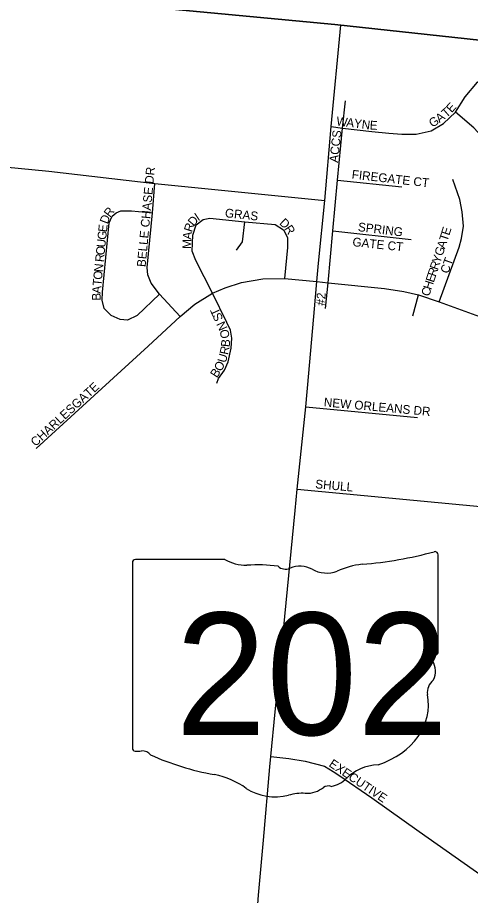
# Model space of a CAD drawing. Extents: x 8.5 to 81.5, y -1.2 to 22.4.
# Drawn here: x 55.233 to 55.722, y 18.242 to 19.189 of the extents above; entities that cross this region are included whole.
import ezdxf

# ---------------------------------------------------------------- set-up
doc = ezdxf.new("R2010")
doc.units = 0
for name, color, linetype in [('GM_X_Adjacent_County', 7, 'Continuous'), ('GM_X_City_Street', 7, 'Continuous'), ('GM_X_City_Street_Text', 7, 'Continuous'), ('GM_X_County', 7, 'Continuous'), ('GM_X_State_Location', 7, 'Continuous'), ('GM_X_State_Route', 7, 'Continuous'), ('GM_X_State_Shield', 7, 'Continuous')]:
    doc.layers.add(name, color=color, linetype=linetype)

msp = doc.modelspace()

# ---------------------------------------------------------------- linework, layer by layer
at = {"layer": 'GM_X_Adjacent_County'}
msp.add_lwpolyline([(54.08792, 21.25055), (53.97517, 21.07964), (53.98925, 20.88787), (54.01131, 20.79217), (54.0509, 20.40525), (54.08743, 20.21352), (54.08516, 20.02178), (54.11826, 19.92611), (54.16353, 19.83082), (54.25825, 19.73401), (54.36439, 19.53926), (54.43857, 19.4436), (54.4557, 19.28681), (54.60716, 19.27259), (55.07099, 19.22961), (55.57538, 19.18184), (55.8177, 19.15565), (56.1419, 19.12062), (56.17199, 19.11737), (56.25272, 19.11082)], dxfattribs=at)
at = {"layer": 'GM_X_City_Street'}
for points in [[(55.57169, 19.07164), (55.58369, 19.07004), (55.61533, 19.06632), (55.63356, 19.06446), (55.64763, 19.06333), (55.66318, 19.06333), (55.67948, 19.06707), (55.69249, 19.07514), (55.70565, 19.08725), (55.71609, 19.10365), (55.72942, 19.11965), (55.7381, 19.12632), (55.75171, 19.13271), (55.76667, 19.13571), (55.7891, 19.13416), (55.81595, 19.1323), (55.8506, 19.12851), (55.8694, 19.12674), (55.88226, 19.12419), (55.89348, 19.11971), (55.90379, 19.11373), (55.91729, 19.10309)], [(55.56538, 18.8755), (55.56829, 18.90321), (55.57316, 18.9591), (55.57842, 19.0138), (55.58369, 19.07004), (55.58695, 19.09958)], [(55.73939, 18.86377), (55.76029, 18.91778), (55.76526, 18.9366), (55.7684, 18.95462), (55.76918, 18.97077), (55.76715, 18.99145), (55.76511, 19.00148), (55.76291, 19.01104), (55.75461, 19.03032), (55.74677, 19.04474), (55.73831, 19.05618), (55.7253, 19.07029), (55.70565, 19.08725)], [(55.06072, 19.04363), (55.26694, 19.02354), (55.38148, 19.01011), (55.5648, 18.99202)], [(55.57842, 19.0138), (55.64766, 19.00671)], [(55.68813, 18.88248), (55.70954, 18.94139), (55.7122, 18.951), (55.71412, 18.96416), (55.71279, 18.97983), (55.71028, 18.99283), (55.70259, 19.01456)], [(55.40875, 18.86686), (55.38638, 18.89072), (55.37728, 18.90263), (55.37399, 18.91164), (55.37309, 18.91954), (55.37888, 18.97873), (55.38148, 19.01011)], [(55.38638, 18.89072), (55.36241, 18.86773), (55.35208, 18.86293), (55.34413, 18.86354), (55.33432, 18.86768), (55.32658, 18.87542), (55.32467, 18.8842), (55.32504, 18.89305), (55.33217, 18.96778), (55.33536, 18.97503), (55.33967, 18.97872), (55.34483, 18.98093), (55.35614, 18.98081), (55.37888, 18.97873)], [(55.44374, 18.89193), (55.42556, 18.92726), (55.42155, 18.93735), (55.42229, 18.95453), (55.42591, 18.96558), (55.43367, 18.97144), (55.44058, 18.97266), (55.47855, 18.96903), (55.51117, 18.96593), (55.51998, 18.96023), (55.52429, 18.95211), (55.52429, 18.94107), (55.52134, 18.90782)], [(55.46955, 18.93838), (55.47574, 18.94715), (55.47855, 18.96903)], [(55.57316, 18.9591), (55.65761, 18.94986)], [(55.25346, 18.72421), (55.37409, 18.83467), (55.40875, 18.86686), (55.4245, 18.88005), (55.44374, 18.89193), (55.45716, 18.89761), (55.47471, 18.90329), (55.49787, 18.90753), (55.52134, 18.90782), (55.55608, 18.90457), (55.56829, 18.90321), (55.62913, 18.89698), (55.65002, 18.89379), (55.66576, 18.8901), (55.68813, 18.88248), (55.73939, 18.86377)], [(55.44813, 18.79493), (55.45009, 18.8), (55.45665, 18.80884), (55.46063, 18.81784), (55.46377, 18.83272), (55.46455, 18.84343), (55.46298, 18.85205), (55.45906, 18.86014), (55.44374, 18.89193)], [(55.65947, 18.86756), (55.66576, 18.8901)], [(55.54437, 18.76916), (55.66446, 18.75788)], [(55.53496, 18.68057), (56.00995, 18.63533), (56.18568, 18.61835), (56.25272, 18.61175)], [(55.50632, 18.39192), (55.52591, 18.38986), (55.54366, 18.38683), (55.56417, 18.3816), (55.57353, 18.37577)], [(55.57353, 18.37577), (55.57986, 18.37183), (55.61551, 18.34747), (55.66625, 18.31115), (55.74396, 18.25649), (55.76539, 18.24108), (55.77957, 18.23131), (55.79264, 18.22401), (55.80461, 18.21865), (55.81782, 18.21383), (55.83282, 18.21053), (55.90274, 18.20337), (56.02308, 18.19186), (56.16825, 18.17705), (56.25272, 18.16886)]]:
    msp.add_lwpolyline(points, dxfattribs=at)
at = {"layer": 'GM_X_County'}
msp.add_lwpolyline([(56.25272, 19.11082), (56.17199, 19.11737), (56.1419, 19.12062), (55.8177, 19.15565), (55.57538, 19.18184), (55.07099, 19.22961), (54.60716, 19.27259), (54.4557, 19.28681), (54.43857, 19.4436), (54.36439, 19.53926), (54.25825, 19.73401), (54.16353, 19.83082), (54.11826, 19.92611), (54.08516, 20.02178), (54.08743, 20.21352), (54.0509, 20.40525), (54.01131, 20.79217), (53.98925, 20.88787), (53.97517, 21.07964), (54.08792, 21.25055)], dxfattribs=at)
at = {"layer": 'GM_X_State_Route'}
for points in [[(55.55804, 18.92428), (55.5648, 18.99202), (55.57169, 19.07164), (55.5821, 19.1812)], [(55.55351, 18.87487), (55.55608, 18.90457), (55.55804, 18.92428)], [(55.54753, 18.80565), (55.55351, 18.87487)], [(55.5327, 18.65753), (55.53496, 18.68057), (55.54437, 18.76916), (55.54753, 18.80565)], [(55.51118, 18.44025), (55.52005, 18.52841), (55.5327, 18.65753)], [(55.50537, 18.38098), (55.50632, 18.39192), (55.51118, 18.44025)], [(55.49847, 18.30188), (55.50537, 18.38098)], [(55.49331, 18.24256), (55.49847, 18.30188)], [(55.48466, 18.15527), (55.49079, 18.21298), (55.49244, 18.23267), (55.49331, 18.24256)]]:
    msp.add_lwpolyline(points, dxfattribs=at)
at = {"layer": 'GM_X_State_Shield'}
for p, q in [((55.45698, 18.6047), (55.36046, 18.6047)), ((55.6868, 18.50498), (55.6868, 18.60966)), ((55.35722, 18.60126), (55.35722, 18.40114)), ((55.68677, 18.505), (55.6868, 18.50498))]:
    msp.add_line(p, q, dxfattribs=at)
for centre, major_axis, start_param, end_param in [((55.5694, 18.87754), (0.34952, 0), 4.814394, 5.042369), ((55.68314, 18.6101), (0.00367, 0), 6.141152, 7.989035), ((55.36099, 18.60169), (0.00382, 0), 1.712693, 3.28349), ((55.47997, 18.62794), (0.03703, 0), 4.042523, 4.731795), ((55.49225, 18.49235), (0.13295, 0), 1.404758, 1.657858), ((55.52243, 18.60272), (0.01068, 0), 3.836095, 5.185415), ((55.53811, 18.57959), (0.02221, 0), 0.950623, 2.079405), ((55.56679, 18.61132), (0.02672, 0), 4.081561, 5.145723), ((55.61398, 18.54358), (0.07032, 0), 1.699011, 2.107814), ((55.68595, 18.49729), (0.00568, 0), 1.883978, 3.671073), ((55.68289, 18.50457), (0.00393, 0), 5.05454, 6.418171), ((55.64983, 18.48406), (0.03409, 0), 5.934695, 6.695948), ((55.69995, 18.46117), (0.0248, 0), 2.387724, 3.262537), ((55.58898, 18.44785), (0.08742, 0), 5.101752, 6.440018), ((55.36103, 18.4007), (0.00385, 0), 3.00124, 4.508301), ((55.36161, 18.42118), (0.0294, 0), 4.665946, 4.897461), ((55.36762, 18.38959), (0.0106, 0), 0.519207, 1.627899), ((55.50145, 18.56939), (0.2524, 0), 4.195997, 4.488961), ((55.62584, 18.34496), (0.04788, 0), 1.647645, 2.488434), ((55.4262, 18.31124), (0.07897, 0), 0.823519, 1.323587), ((55.56518, 18.38174), (0.02824, 0), 4.937069, 5.64225), ((55.51161, 18.3886), (0.05011, 0), 4.026481, 4.996735), ((55.54423, 18.37362), (0.0267, 0), 4.691044, 5.507374), ((55.56838, 18.35423), (0.00752, 0), 1.147584, 2.315152), ((55.54057, 18.31941), (0.04118, 0), 1.495662, 1.94098)]:
    msp.add_ellipse(centre, major_axis=major_axis, ratio=0.8, start_param=start_param, end_param=end_param, dxfattribs=at)

# ---------------------------------------------------------------- texts
at = {"layer": 'GM_X_City_Street_Text'}
for s, height, rotation, p in [('E', 0.00947, 47.61839, (55.70142, 19.08601)), ('T', 0.00947, 41.53891, (55.69565, 19.08082)), ('W', 0.00947, 352.90418, (55.57668, 19.0731)), ('A', 0.00947, 352.89939, (55.58743, 19.07176)), ('Y', 0.00947, 352.89939, (55.5957, 19.07073)), ('N', 0.00947, 352.89939, (55.60397, 19.0697)), ('E', 0.00947, 356.21628, (55.61283, 19.06861)), ('G', 0.00947, 31.84089, (55.68052, 19.07035)), ('A', 0.00947, 37.09025, (55.68838, 19.07529)), ('ACCS', 0.00947, 83.66313, (55.57884, 19.03236)), ('BELLE CHASE DR', 0.0094697, 84.5835, (55.37134, 18.91985)), ('FIREGATE CT', 0.0094697, 353.51537, (55.59331, 19.0156)), ('R', 0.00947, 52.81929, (55.33304, 18.97307)), ('GRAS', 0.00947, 353.92637, (55.45663, 18.97394)), ('D', 0.00947, 69.33907, (55.33045, 18.9659)), ('D', 0.00947, 49.98178, (55.42329, 18.96348)), ('I', 0.00947, 34.05376, (55.42813, 18.9694)), ('D', 0.00947, 316.03545, (55.515, 18.96695)), ('E', 0.00947, 84.06105, (55.32965, 18.95741)), ('R', 0.00947, 71.97967, (55.42143, 18.95718)), ('R', 0.00947, 302.8009, (55.52063, 18.96161)), ('SPRING', 0.00947, 353.01832, (55.6, 18.95893)), ('E', 0.00947, 72.54791, (55.69886, 18.95362)), ('G', 0.00947, 84.06536, (55.32879, 18.94912)), ('A', 0.00947, 84.19806, (55.4207, 18.94941)), ('T', 0.00947, 71.76221, (55.69673, 18.94715)), ('U', 0.00947, 84.07856, (55.32793, 18.94084)), ('M', 0.00947, 88.76135, (55.4205, 18.93961)), ('GATE CT', 0.00947, 354.0936, (55.59412, 18.94273)), ('A', 0.00947, 71.72402, (55.69412, 18.93924)), ('O', 0.00947, 84.04362, (55.32706, 18.93254)), ('G', 0.00947, 71.74243, (55.69151, 18.93132)), ('R', 0.00947, 84.0647, (55.32629, 18.92508)), ('R', 0.00947, 71.76316, (55.68654, 18.91629)), ('Y', 0.00947, 71.72402, (55.68889, 18.92341)), ('CT', 0.00947, 70.56063, (55.69777, 18.91234)), ('O', 0.00947, 84.04362, (55.3243, 18.90601)), ('N', 0.00947, 84.07856, (55.32517, 18.91431)), ('R', 0.00947, 71.71865, (55.68419, 18.90916)), ('T', 0.00947, 84.22414, (55.32363, 18.89939)), ('E', 0.00947, 71.74644, (55.6821, 18.90283)), ('A', 0.00947, 86.04052, (55.32306, 18.89116)), ('C', 0.00947, 71.71865, (55.67713, 18.88779)), ('H', 0.00947, 71.75642, (55.67949, 18.89491)), ('B', 0.00947, 89.41709, (55.32299, 18.8838)), ('#2', 0.00947, 85.9166, (55.56467, 18.87812)), ('T', 0.00947, 114.45074, (55.45259, 18.87017)), ('S', 0.00947, 114.548, (55.45536, 18.86412)), ('N', 0.00947, 114.64652, (55.45987, 18.85427)), ('O', 0.00947, 103.18482, (55.46245, 18.8442)), ('B', 0.00947, 84.94785, (55.46202, 18.83346)), ('R', 0.00947, 78.17551, (55.4603, 18.82491)), ('U', 0.00947, 73.38142, (55.4577, 18.81609)), ('O', 0.00947, 60.79633, (55.45275, 18.80673)), ('B', 0.00947, 56.97002, (55.44831, 18.79985)), ('CHARLESGATE', 0.0094697, 42.58031, (55.25274, 18.72598)), ('NEW ORLEANS DR', 0.0094697, 354.84887, (55.56327, 18.76977)), ('SHULL', 0.00947, 354.92296, (55.5541, 18.68144)), ('EXECUTIVE', 0.00947, 325.90783, (55.56825, 18.38199))]:
    msp.add_text(s, height=height, rotation=rotation, dxfattribs=at).set_placement(p)
at = {"layer": 'GM_X_State_Location'}
for s in ['s', 'r']:
    msp.add_text(s, height=0.000189, dxfattribs=at).set_placement((55.5183, 18.4879))
msp.add_text('202', height=0.000189, rotation=0.00001, dxfattribs=at).set_placement((55.45144, 18.47412))
at = {"layer": 'GM_X_State_Shield'}
msp.add_text('202', height=0.131836, dxfattribs=at).set_placement((55.40356, 18.41525))

doc.saveas('drawing.dxf')
